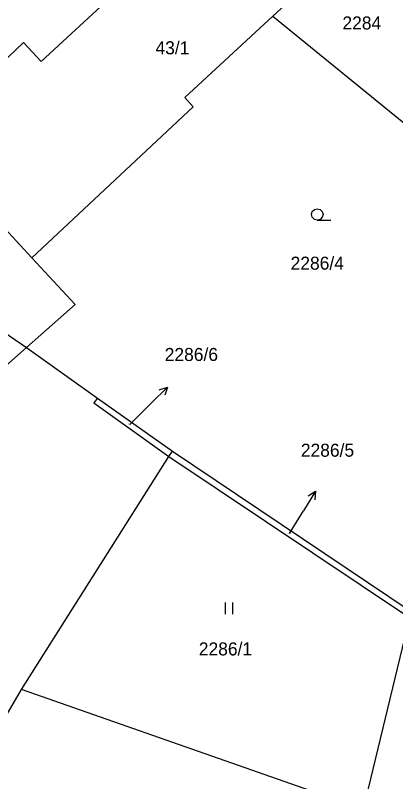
# Model space of a CAD drawing. Extents: x -747792 to -745414, y -1093712 to -1091463.
# Drawn here: x -746621.4 to -746596.6, y -1093052.6 to -1093002.6 of the extents above; entities that cross this region are included whole.
import ezdxf

# ---------------------------------------------------------------- set-up
doc = ezdxf.new("R2010")
doc.units = 0
for name, color, linetype in [('Budovy', 7, 'Continuous'), ('Doplňkové značky', 7, 'Continuous'), ('Koleje_dopravní prvky', 7, 'Continuous'), ('Stromy_porost', 7, 'Continuous')]:
    doc.layers.add(name, color=color, linetype=linetype)

msp = doc.modelspace()

# ---------------------------------------------------------------- linework, layer by layer
at = {"layer": 'Budovy'}
for points in [[(-746601.7, -1093015.96), (-746601.89, -1093015.91), (-746602.025, -1093015.77), (-746602.075, -1093015.585), (-746602.025, -1093015.4), (-746601.89, -1093015.26), (-746601.7, -1093015.21), (-746601.51, -1093015.26), (-746601.375, -1093015.4), (-746601.325, -1093015.585), (-746601.375, -1093015.77), (-746601.51, -1093015.91), (-746601.7, -1093015.96), (-746600.825, -1093015.96)], [(-746607.7, -1093040.92), (-746607.7, -1093041.67)], [(-746607.2, -1093041.67), (-746607.2, -1093040.92)]]:
    msp.add_lwpolyline(points, dxfattribs=at)
at = {"layer": 'Doplňkové značky'}
for points in [[(-746611.469, -1093026.85), (-746612.53, -1093027.91)], [(-746611.999, -1093027.026), (-746611.469, -1093026.85), (-746611.646, -1093027.38)], [(-746613.92, -1093029.3), (-746612.53, -1093027.91)], [(-746601.821, -1093033.658), (-746602.6, -1093034.94)], [(-746602.294, -1093033.956), (-746601.821, -1093033.658), (-746601.867, -1093034.215)], [(-746603.5, -1093036.42), (-746602.6, -1093034.94)]]:
    msp.add_lwpolyline(points, dxfattribs=at)
at = {"layer": 'Stromy_porost'}
for points in [[(-746595.89, -1092994.6), (-746604.59, -1093002.65)], [(-746610.19, -1092996.78), (-746619.71, -1093005.59)], [(-746604.59, -1093002.65), (-746610.34, -1093007.96)], [(-746604.59, -1093002.65), (-746583.3, -1093020)], [(-746620.85, -1093004.36), (-746622.93, -1093006.31)], [(-746619.71, -1093005.59), (-746620.85, -1093004.36)], [(-746610.34, -1093007.96), (-746609.8, -1093008.55)], [(-746620.31, -1093018.41), (-746609.8, -1093008.55)], [(-746620.31, -1093018.41), (-746626.42, -1093011.8)], [(-746620.31, -1093018.41), (-746617.48, -1093021.47)], [(-746624.42, -1093021.7), (-746620.66, -1093024.28)], [(-746620.66, -1093024.28), (-746617.48, -1093021.47)], [(-746620.66, -1093024.28), (-746626.11, -1093029.1)], [(-746620.66, -1093024.28), (-746616.02, -1093027.57)], [(-746616.02, -1093027.57), (-746616.27, -1093027.88)], [(-746616.02, -1093027.57), (-746611.15, -1093031.03)], [(-746616.27, -1093027.88), (-746611.37, -1093031.38)], [(-746611.37, -1093031.38), (-746611.15, -1093031.03)], [(-746611.15, -1093031.03), (-746595.58, -1093041.5)], [(-746620.99, -1093046.6), (-746611.37, -1093031.38)], [(-746611.37, -1093031.38), (-746595.68, -1093041.9)], [(-746595.68, -1093041.9), (-746598.7, -1093054.4)], [(-746625.75, -1093054.73), (-746620.99, -1093046.6)], [(-746598.7, -1093054.4), (-746620.99, -1093046.6)]]:
    msp.add_lwpolyline(points, dxfattribs=at)

# ---------------------------------------------------------------- texts
at = {"layer": 'Doplňkové značky'}
for s, p in [('2286/6', (-746611.648, -1093025.15)), ('2286/5', (-746602.772, -1093031.4))]:
    msp.add_text(s, height=0.85, dxfattribs=at).set_placement(p)
at = {"layer": 'Koleje_dopravní prvky'}
for s, height, p in [('2284', 0.85, (-746600.059, -1093003.51)), ('43/1', 0.85, (-746612.251, -1093005.13)), ('2286/4', 0.85, (-746603.438, -1093019.19)), ('2286/6', 0.05, (-746614.046, -1093029.3)), ('2286/5', 0.05, (-746603.628, -1093036.42)), ('2286/1', 0.85, (-746609.424, -1093044.37))]:
    msp.add_text(s, height=height, dxfattribs=at).set_placement(p)

doc.saveas('drawing.dxf')
